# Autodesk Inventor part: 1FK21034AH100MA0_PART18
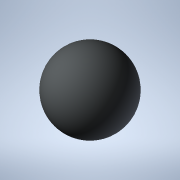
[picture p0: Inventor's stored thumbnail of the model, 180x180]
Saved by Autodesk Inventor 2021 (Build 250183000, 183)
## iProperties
Created: 2025-04
Part Number: 1FK21034AH100MA0_PART18
Material: Generic
Catalog Web Link: www.3dfindit.com
Description: -Servo synchronous motor
Document SubType Name: Modeling
Designer: psAdmin
Mass: 0.113097 g
Surface Area: 1.13097 cm^2
Volume: 0.113097 cm^3
Density: 1 g/cm^3
Appearance: PSOLRGB-212-217-219
Category: PARTsolutions
Title: 1FK21034AH100MA0_PART18
Author: Cadenas PARTsolutions
Comments: Servo synchronous motor
Sending System: PARTsolutions
Preprocessor: ST-DEVELOPER v19.3
PSOL_IDENT_0: {$CADENAS_DATA/23d-libs/siemens_ag/_cat_/39/97/1fk21034ah100ma0.prj},216 {VTYP=3D},{NB=1FK21034AH100
PSOL_IDENT_1: MA0_PART18},{LINA=1FK21034AH100MA0_PART18},{NN=1FK21034AH100MA0_PART18},{NOPRJ=TRUE},{DATE=19.08.202
PSOL_IDENT_2: 5 14:00:33},{GEOMDATE=30.07.2025 02:02:21},{VERSION=},{LINEID=10},{WBVAR=},{WBNUMERIC=}  {NB=1FK2103
PSOL_IDENT_3: 4AH100MA0_PART18},{LINA=1FK21034AH100MA0_PART18},{KT=DUMMY},{PREVIEW=../../../_pool_/d3/78/p_d211_xx
PSOL_IDENT_4: _00934j.png},{DESCSHORT=SIMOTICS S-1FK2 HD, SINAMICS S210 3AC 400V-480V, 1.01 Nm, 4500 rpm},{DESCLON
PSOL_IDENT_5: G=SIMOTICS S-1FK2 HD servo motor M0=1.27 Nm; PN = 0.48 kW at nN=4500 rpm (380-480 V); PN = 0.3 kW at
PSOL_IDENT_6: nN=2500 rpm (200-240 V); with holding brake; degree of protection IP64; cylindrical shaft D14 x 30
PSOL_IDENT_7: mm; absolute encoder 22-bit + 12-bit multiturn (encoder AM22DQC); with OCC interface; plug size M17,
PSOL_IDENT_8: rotatable; SIMOTICS S-1FK2 servomotorfor a wide range of uses in industrial environments. SIMOTICS
PSOL_IDENT_9: S‑1FK2 servomotors are compact synchronous motors with a high dynamic performance that set themselve
PSOL_IDENT_10: s apart as a result of their high power density, degree of protection and overload capability. The m
PSOL_IDENT_11: otors are available in two variants: as High Dynamic variant (highest dynamic performance as a resul
PSOL_IDENT_12: t of the low intrinsic moment of inertia for applications demanding a high dynamic performance with
PSOL_IDENT_13: low moved masses) - and as Compact variant (precise and stable closed-loop control for medium up to
PSOL_IDENT_14: large moved masses as a result of a medium intrinsic moment of inertia). SIMOTICSS‑1FK2 servomotors
PSOL_IDENT_15: fully exploit their strengths in a system with the SINAMICSS210 frequency converter and simple conne
PSOL_IDENT_16: ction using the one cable connection (OCC). Advantages include the short control and positioning tim
PSOL_IDENT_17: es, fast and precise correction of disturbing quantities as well as stable control with a high dynam
PSOL_IDENT_18: ic performance. The servo motors can be configured to address a wide range of requirements. For exam
PSOL_IDENT_19: ple with and without holding brake, IP64 or IP65 degree of protection, singleturn or multiturn absol
PSOL_IDENT_20: ute encoders - to name just a few. Further, the servomotors are available in different shaft heights
PSOL_IDENT_21: extending from 20 to 100. A shaft sealing ring is available to achieve an IP65 degree of protection
PSOL_IDENT_22: and for subsequent mounting at the motor or as spare part. SIMOTICS - the optimum motor for each an
PSOL_IDENT_23: d every motion control application.},{INTNO=195125454019},{SUPPLIERALTNO=1FK2103-4AH10-0MA0},{MANUID=
PSOL_IDENT_24: 1FK21034AH100MA0},{MANUNAME=Siemens},{MANUTYPEDESC=SYNCHRONOUS MOTOR 1FK2 HD 1,27 NM},{AAU732=SIMOTI
PSOL_IDENT_25: CS},{AAO057=S-1FK2},{AAU734=SIMOTICS S-1FK2 HD servo motor M0=1.27 Nm; PN = 0.48 kW at nN=4500 rpm (
PSOL_IDENT_26: 380-480 V); PN = 0.3 kW at nN=2500 rpm (200-240 V); with holding brake; degree of protection IP64; c
PSOL_IDENT_27: ylindrical shaft D14 x 30 mm; absolute encoder 22-bit + 12-bit multiturn (encoder AM22DQC); with OCC
PSOL_IDENT_28: interface; plug size M17, rotatable;},{AAW338=SYNCHRONOUS MOTOR 1FK2 HD 1,27 NM},{AAO742=SIMOTICS},
PSOL_IDENT_29: {AAO663=4034106444921},{NOCUPEROU=1},{PRICEQUANTITY=1},{QUANTITYMIN=1},{QUANTITYINT=1},{CTN=85015100
PSOL_IDENT_30: },{COO=RO},{AAO676=1FK2103-4AH10-0MA0},{AAO677=Siemens AG},{ORDERUNIT=C62},{CONTENTUNIT=C62}
NB: 1FK21034AH100MA0_PART18
NT: Servo synchronous motor
NBSYN: $MANUID._PART18
LINA: 1FK21034AH100MA0_PART18
CATALOG: SIEMENS
PREVIEW: ../../../_pool_/d3/78/p_d211_xx_00934j.png
DESCSHORT: SIMOTICS S-1FK2 HD, SINAMICS S210 3AC 400V-480V, 1.01 Nm, 4500 rpm
DESCLONG: SIMOTICS S-1FK2 HD servo motor M0=1.27 Nm; PN = 0.48 kW at nN=4500 rpm (380-480 V); PN = 0.3 kW at nN=2500 rpm (200-240 V); with holding brake; degree of protec
INTNO: 195125454019
SUPPLIERALTNO: 1FK2103-4AH10-0MA0
MANUID: 1FK21034AH100MA0
MANUNAME: Siemens
MANUTYPEDESC: SYNCHRONOUS MOTOR 1FK2 HD 1,27 NM
AAU732: SIMOTICS
AAO057: S-1FK2
AAU734: SIMOTICS S-1FK2 HD servo motor M0=1.27 Nm; PN = 0.48 kW at nN=4500 rpm (380-480 V); PN = 0.3 kW at nN=2500 rpm (200-240 V); with holding brake; degree of protec
AAW338: SYNCHRONOUS MOTOR 1FK2 HD 1,27 NM
AAO742: SIMOTICS
AAO663: 4034106444921.0
NOCUPEROU: 1
PRICEQUANTITY: 1
QUANTITYMIN: 1
QUANTITYINT: 1
CTN: 85015100
COO: RO
ARTICLENO: 1FK21034AH100MA0_PART18
BOMINFO: 1FK21034AH100MA0_PART18
CREATOR: CADENAS GmbH
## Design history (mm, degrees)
feature "2025_04_17_15_09_00_0361"
body "Solid1"
